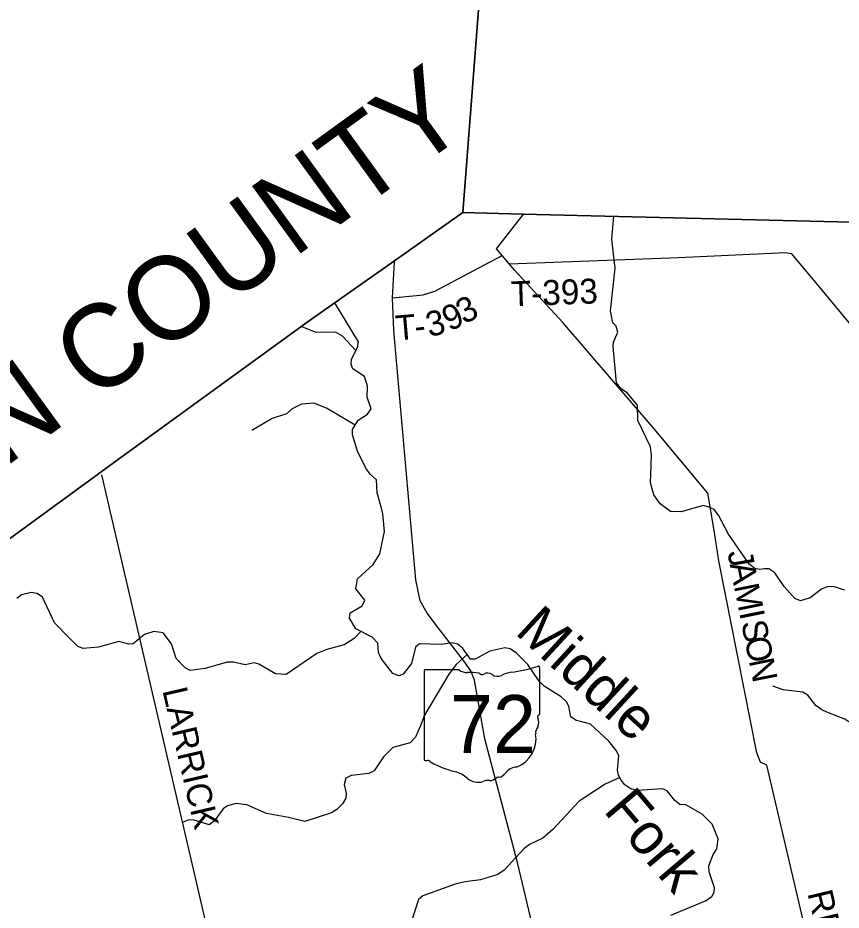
# Model space of a CAD drawing. Extents: x 1525783 to 1900577, y 218250 to 627376.
# Drawn here: x 1654768 to 1664681, y 495597 to 506340 of the extents above; entities that cross this region are included whole.
import ezdxf

# ---------------------------------------------------------------- set-up
doc = ezdxf.new("R2010")
doc.units = 0
for name, color, linetype in [('GM_X_Adjacent_County', 7, 'Continuous'), ('GM_X_Adjacent_County_Text', 7, 'Continuous'), ('GM_X_County', 7, 'Continuous'), ('GM_X_County_Road', 7, 'Continuous'), ('GM_X_County_Road_Text', 7, 'Continuous'), ('GM_X_Minor_River', 7, 'Continuous'), ('GM_X_Minor_River_Text', 7, 'Continuous'), ('GM_X_State_Location', 7, 'Continuous'), ('GM_X_State_Route', 7, 'Continuous'), ('GM_X_State_Shield', 7, 'Continuous'), ('GM_X_Township', 7, 'Continuous'), ('GM_X_Township_Road', 7, 'Continuous'), ('GM_X_Township_Road_Text', 7, 'Continuous')]:
    doc.layers.add(name, color=color, linetype=linetype)

msp = doc.modelspace()

# ---------------------------------------------------------------- linework, layer by layer
at = {"layer": 'GM_X_Adjacent_County'}
for points in [[(1662403, 533380), (1661469, 521334), (1661161, 517359), (1661136, 517041), (1660679, 511141), (1660668, 511007), (1660124, 503996), (1659262, 503388), (1658265, 502686), (1655787, 500886), (1655741, 500852), (1648788, 495779)], [(1704437, 503092), (1698641, 503176), (1693676, 503248), (1687539, 503338), (1685835, 503363), (1685430, 503373), (1682405, 503448), (1678903, 503534), (1673166, 503675), (1669035, 503777), (1664966, 503877), (1660848, 503978), (1660124, 503996), (1660668, 511007), (1660679, 511141), (1661136, 517041), (1661161, 517359), (1661469, 521334), (1662403, 533380)]]:
    msp.add_lwpolyline(points, dxfattribs=at)
at = {"layer": 'GM_X_County'}
msp.add_lwpolyline([(1648788, 495779), (1655741, 500852), (1655787, 500886), (1658265, 502686), (1659262, 503388), (1660124, 503996), (1660848, 503978), (1664966, 503877), (1669035, 503777), (1673166, 503675), (1678903, 503534), (1682405, 503448), (1685430, 503373), (1685835, 503363), (1687539, 503338), (1693676, 503248), (1698641, 503176), (1704437, 503092)], dxfattribs=at)
at = {"layer": 'GM_X_County_Road'}
msp.add_lwpolyline([(1657716, 492498), (1655780, 500837)], dxfattribs=at)
at = {"layer": 'GM_X_Minor_River'}
for points in [[(1661972, 502628), (1661933, 502670), (1661903, 502814), (1661958, 503325), (1661940, 503499), (1661921, 503676), (1661943, 503952)], [(1663199, 496454), (1663129, 496634), (1663008, 496754), (1662811, 496864), (1662737, 496867), (1662678, 496916), (1662585, 497032), (1662529, 497056), (1662225, 497039), (1662149, 497058), (1662076, 497104), (1662033, 497162), (1661999, 497221), (1661988, 497281), (1662005, 497454), (1661976, 497514), (1661883, 497630), (1661661, 497836), (1661541, 497870), (1661489, 497881), (1661428, 497924), (1661404, 498053), (1661374, 498107), (1661311, 498167), (1661104, 498292), (1661045, 498353), (1660907, 498554), (1660773, 498692), (1660697, 498742), (1660631, 498755), (1660452, 498715), (1660274, 498618), (1660219, 498619), (1660125, 498748), (1660064, 498798), (1659996, 498817), (1659871, 498794), (1659606, 498803), (1659555, 498763), (1659506, 498565), (1659409, 498438), (1659357, 498419), (1659283, 498446), (1659143, 498627), (1659112, 498698), (1659104, 498812), (1659036, 498884), (1658837, 498983), (1658761, 499114), (1658768, 499177), (1658914, 499259), (1658945, 499330), (1658837, 499466), (1658857, 499586), (1659048, 499758), (1659126, 499885), (1659183, 500157), (1659164, 500368), (1659145, 500437), (1659096, 500620), (1659086, 500779), (1659011, 500848), (1658958, 500919), (1658859, 501123), (1658797, 501319), (1658796, 501383), (1658866, 501496), (1658978, 501569), (1659021, 501632), (1658973, 501775), (1658977, 501904), (1658943, 502023), (1658800, 502113), (1658781, 502168), (1658784, 502232), (1658856, 502373), (1658869, 502439), (1658585, 502910)], [(1658837, 502336), (1658677, 502508), (1658592, 502556), (1658361, 502553), (1658181, 502624)], [(1664724, 499448), (1664586, 499493), (1664514, 499490), (1664443, 499461), (1664307, 499356), (1664192, 499322), (1664122, 499351), (1663995, 499494), (1663883, 499658), (1663812, 499705), (1663762, 499708), (1663697, 499697), (1663643, 499710), (1663576, 499759), (1663324, 500124), (1663203, 500352), (1663150, 500419), (1663080, 500452), (1663020, 500469), (1662754, 500391), (1662628, 500395), (1662502, 500489), (1662424, 500599), (1662386, 500740), (1662388, 500848), (1662397, 501069), (1662387, 501177), (1662233, 501491), (1662228, 501677), (1662104, 501824), (1662038, 501871), (1661975, 501944), (1661934, 502384), (1661938, 502436), (1661992, 502554), (1661972, 502628)], [(1658829, 501435), (1658483, 501639), (1658333, 501701), (1658183, 501689), (1658073, 501633), (1658002, 501572), (1657830, 501516), (1657587, 501371)], [(1658898, 498952), (1658817, 498869), (1658698, 498792), (1658488, 498736), (1658369, 498685), (1657997, 498434), (1657871, 498442), (1657670, 498560), (1657614, 498576), (1657507, 498552), (1657363, 498582), (1657288, 498581), (1657024, 498505), (1656843, 498482), (1656781, 498513), (1656674, 498625), (1656619, 498804), (1656516, 498936), (1656406, 498952), (1656293, 498916), (1656226, 498861), (1656155, 498803), (1656105, 498798), (1655985, 498830), (1655738, 498764), (1655555, 498749), (1655491, 498770), (1655387, 498876), (1655211, 499055), (1655067, 499364), (1655001, 499411), (1654929, 499420), (1654812, 499392), (1654757, 499349)], [(1660180, 498674), (1660046, 498555), (1659956, 498438), (1659663, 497945), (1659612, 497809), (1659558, 497680), (1659491, 497611), (1659285, 497556), (1659171, 497443), (1659057, 497274), (1658995, 497243), (1658781, 497218), (1658719, 497187), (1658697, 497109), (1658722, 497005), (1658717, 496944), (1658678, 496877), (1658610, 496810), (1658543, 496769), (1658222, 496663), (1658092, 496697), (1658028, 496714), (1657762, 496759), (1657524, 496865), (1657398, 496881), (1657291, 496852), (1657241, 496817), (1657183, 496739), (1657136, 496672), (1657073, 496625), (1656881, 496686), (1656813, 496681), (1656744, 496648)], [(1666190, 498045), (1666049, 497978), (1665881, 497798), (1665761, 497711), (1665699, 497694), (1665594, 497706), (1665532, 497691), (1665354, 497599), (1665130, 497548), (1665074, 497549), (1665010, 497572), (1664956, 497619), (1664797, 497848), (1664724, 497897), (1664510, 497981), (1664450, 498010), (1664375, 498059), (1664280, 498187), (1664219, 498222), (1663984, 498248), (1663860, 498292)], [(1662016, 497192), (1661839, 497113), (1661526, 496911), (1661210, 496569), (1661090, 496463), (1660928, 496387), (1660861, 496334), (1660624, 496079), (1660546, 496026), (1660337, 495961), (1660153, 495937), (1660034, 495909), (1659645, 495769), (1659592, 495725), (1659513, 495476)], [(1662632, 495536), (1663048, 495710), (1663125, 495763), (1663150, 495815), (1663157, 495867), (1663092, 496059), (1663089, 496129), (1663139, 496267), (1663183, 496334), (1663199, 496454)]]:
    msp.add_lwpolyline(points, dxfattribs=at)
at = {"layer": 'GM_X_State_Route'}
msp.add_lwpolyline([(1660811, 492461), (1660783, 492667), (1660739, 492979), (1660735, 493138), (1660764, 493341), (1660817, 493712), (1660881, 494191), (1660973, 494628), (1661010, 494836), (1661019, 495014), (1660999, 495258), (1660785, 496172), (1660390, 497660), (1660268, 498365), (1660221, 498478), (1660146, 498588), (1659819, 499009), (1659695, 499173), (1659612, 499323), (1659560, 499573), (1659296, 502575), (1659280, 502971), (1659302, 503401)], dxfattribs=at)
at = {"layer": 'GM_X_State_Shield'}
for p, q in [((1660081, 498490), (1659673, 498490)), ((1661052, 497963), (1661052, 498516)), ((1659659, 498472), (1659659, 497415)), ((1661051, 497964), (1661052, 497963))]:
    msp.add_line(p, q, dxfattribs=at)
for centre, radius, start, end in [((1659675, 498474), 16.1, 98.1301, 188.1301), ((1660178, 498613), 156, 231.6195, 271.1119), ((1660556, 499931), 1476, 275.8445, 288.9065), ((1661036, 498518), 15.5, 351.8621, 97.738), ((1660230, 497897), 562, 80.4867, 94.9883), ((1660357, 498480), 45.1, 219.7921, 297.1024), ((1660423, 498357), 93.8, 54.4667, 119.1411), ((1660545, 498525), 113, 233.8562, 294.8282), ((1660744, 498167), 297, 97.3462, 120.7689), ((1661035, 497961), 16.6, 289.6038, 7.7341), ((1661048, 497923), 24, 107.944, 210.337), ((1660895, 497853), 144, 340.033, 23.6496), ((1661107, 497732), 105, 136.8065, 186.9296), ((1660638, 497662), 369, 292.3089, 8.9858), ((1659675, 497413), 16.3, 171.9584, 258.3066), ((1659678, 497521), 124, 267.339, 280.6039), ((1659703, 497354), 44.8, 29.7484, 93.2717), ((1660269, 498304), 1066, 240.4129, 257.1985), ((1660794, 497119), 202, 94.4031, 142.5768), ((1659951, 496940), 334, 47.1842, 75.836), ((1660538, 497313), 119, 282.8732, 323.2771), ((1660312, 497349), 212, 230.7004, 286.2918), ((1660434, 496984), 174, 85.6951, 111.2099), ((1660449, 497270), 113, 268.777, 315.5493), ((1660551, 497167), 31.8, 65.7517, 132.6484)]:
    msp.add_arc(centre, radius, start, end, dxfattribs=at)
at = {"layer": 'GM_X_Township'}
msp.add_lwpolyline([(1648788, 495779), (1655741, 500852), (1655787, 500886), (1658265, 502686), (1659262, 503388), (1660124, 503996), (1660848, 503978), (1664966, 503877), (1669035, 503777), (1673166, 503675), (1678903, 503534), (1682405, 503448)], dxfattribs=at)
at = {"layer": 'GM_X_Township_Road'}
for points in [[(1664517, 494223), (1663784, 497342), (1663708, 497377), (1663664, 497492), (1663208, 499802), (1663150, 500166), (1663074, 500616), (1662430, 501390), (1661329, 502674), (1660752, 503300), (1660683, 503380), (1660601, 503478), (1660532, 503558), (1660860, 503979)], [(1659280, 502971), (1659649, 503006), (1659788, 503049), (1660601, 503478)], [(1660683, 503380), (1662724, 503454), (1663928, 503512), (1664007, 503515), (1664079, 503503), (1664434, 503081), (1664837, 502593), (1664978, 502483)]]:
    msp.add_lwpolyline(points, dxfattribs=at)

# ---------------------------------------------------------------- texts
at = {"layer": 'GM_X_Adjacent_County_Text'}
msp.add_text('CLINTON COUNTY', height=1000, rotation=35.9139, dxfattribs=at).set_placement((1650624, 498036))
at = {"layer": 'GM_X_County_Road_Text'}
msp.add_text('LARRICK', height=300, rotation=283.1241, dxfattribs=at).set_placement((1656507, 498244))
at = {"layer": 'GM_X_Minor_River_Text'}
for s, rotation, p in [('Middle', 317.404, (1660741, 498933)), ('Fork', 310.2908, (1661808, 496792))]:
    msp.add_text(s, height=500, rotation=rotation, dxfattribs=at).set_placement(p)
at = {"layer": 'GM_X_State_Location'}
for s in ['s', 'r']:
    msp.add_text(s, height=1, dxfattribs=at).set_placement((1660340, 497873))
msp.add_text('72', height=1, rotation=0, dxfattribs=at).set_placement((1660088, 497800))
at = {"layer": 'GM_X_State_Shield'}
msp.add_text('72', height=696.1, dxfattribs=at).set_placement((1659971, 497490))
at = {"layer": 'GM_X_Township_Road_Text'}
for s, rotation, p in [('T-393', 1.9642, (1660709, 502867)), ('9', 25.7688, (1659967, 502561)), ('3', 27.5373, (1660142, 502646)), ('3', 13.3561, (1659720, 502495)), ('T', 4.9432, (1659327, 502455)), ('-', 6.2995, (1659558, 502475)), ('J', 279.6689, (1663312, 499908)), ('A', 281.1941, (1663337, 499761)), ('M', 281.344, (1663388, 499501)), ('I', 281.3467, (1663452, 499182)), ('S', 281.3388, (1663476, 499061)), ('O', 281.3443, (1663516, 498862)), ('N', 281.3407, (1663568, 498603)), ('RD', 283.4381, (1664273, 495802))]:
    msp.add_text(s, height=300, rotation=rotation, dxfattribs=at).set_placement(p)

doc.saveas('drawing.dxf')
